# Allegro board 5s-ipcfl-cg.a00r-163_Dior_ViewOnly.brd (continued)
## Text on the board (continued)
BOTTOM: list("[Physical] BOTTOM" "210.Pad/Pad Direct Connect" "NOT_ALLOWED [(GND_20)]" "ALL_ALLOWED" "" "DRC ERROR CLASS/BOTTOM" "[SmdPin] GND (<uTiL>cId5786<uTiL>.33) (-2968.74 1.19)" "[ThruPin] GND (<uTiL>cId5786<uTiL>.35) (-3027.74 60.19)" list(-3027.740000 60.190000) nil)@@@list("eric2_tseng" "2019/01/23 17:34:51" nil "p143000044-pc" "5s-ipcfl-cg.a00r")@@@list("doris_chen" "2019/01/24 12:53:11" nil "p16c000356-pc" "5s-ipcfl-cg.a00r-chk") | list("[Physical] BOTTOM" "224.Pad/Pad Direct Connect" "NOT_ALLOWED [(GND_20)]" "ALL_ALLOWED" "" "DRC ERROR CLASS/BOTTOM" "[SmdPin] GND (<uTiL>cId5786<uTiL>.33) (-2968.74 1.19)" "[ThruPin] GND (<uTiL>cId5786<uTiL>.37) (-3027.74 -57.81)" list(-3027.740000 -57.810000) nil)@@@list("eric2_tseng" "2019/01/23 17:34:51" nil "p143000044-pc" "5s-ipcfl-cg.a00r")@@@list("doris_chen" "2019/01/24 12:53:19" nil "p16c000356-pc" "5s-ipcfl-cg.a00r-chk") | list("[Physical] BOTTOM" "234.Pad/Pad Direct Connect" "NOT_ALLOWED [(GND_20)]" "ALL_ALLOWED" "" "DRC ERROR CLASS/BOTTOM" "[SmdPin] GND (<uTiL>cId5786<uTiL>.33) (-2968.74 1.19)" "[ThruPin] GND (<uTiL>cId5786<uTiL>.34) (-2909.74 60.19)" list(-2909.740000 60.190000) nil)@@@list("eric2_tseng" "2019/01/23 17:34:51" nil "p143000044-pc" "5s-ipcfl-cg.a00r")@@@list("doris_chen" "2019/01/24 12:53:32" nil "p16c000356-pc" "5s-ipcfl-cg.a00r-chk") | list("[Physical] BOTTOM" "246.Pad/Pad Direct Connect" "NOT_ALLOWED [(GND_20)]" "ALL_ALLOWED" "" "DRC ERROR CLASS/BOTTOM" "[SmdPin] GND (<uTiL>cId5786<uTiL>.33) (-2968.74 1.19)" "[ThruPin] GND (<uTiL>cId5786<uTiL>.36) (-2909.74 -57.81)" list(-2909.740000 -57.810000) nil)@@@list("eric2_tseng" "2019/01/23 17:34:50" nil "p143000044-pc" "5s-ipcfl-cg.a00r")@@@list("doris_chen" "2019/01/24 12:53:38" nil "p16c000356-pc" "5s-ipcfl-cg.a00r-chk") | list("[Physical] BOTTOM" "223.Pad/Pad Direct Connect" "NOT_ALLOWED [(GND_20)]" "ALL_ALLOWED" "" "DRC ERROR CLASS/BOTTOM" "[SmdPin] GND (<uTiL>cId23<uTiL>.33) (-2750.0 2795.0)" "[ThruPin] GND (<uTiL>cId23<uTiL>.37) (-2790.5 2835.5)" list(-2790.500000 2835.500000) nil)@@@list("eric2_tseng" "2019/01/23 17:34:50" nil "p143000044-pc" "5s-ipcfl-cg.a00r")@@@list("doris_chen" "2019/01/24 12:53:18" nil "p16c000356-pc" "5s-ipcfl-cg.a00r-chk") | list("[Physical] BOTTOM" "222.Pad/Pad Direct Connect" "NOT_ALLOWED [(GND_20)]" "ALL_ALLOWED" "" "DRC ERROR CLASS/BOTTOM" "[ThruPin] GND (<uTiL>cId23<uTiL>.41) (-2790.5 2754.5)" "[SmdPin] GND (<uTiL>cId23<uTiL>.33) (-2750.0 2795.0)" list(-2790.500000 2754.500000) nil)@@@list("eric2_tseng" "2019/01/23 17:34:54" nil "p143000044-pc" "5s-ipcfl-cg.a00r")@@@list("doris_chen" "2019/01/24 12:53:18" nil "p16c000356-pc" "5s-ipcfl-cg.a00r-chk") | list("[Physical] BOTTOM" "244.Pad/Pad Direct Connect" "NOT_ALLOWED [(GND_20)]" "ALL_ALLOWED" "" "DRC ERROR CLASS/BOTTOM" "[SmdPin] GND (<uTiL>cId23<uTiL>.33) (-2750.0 2795.0)" "[ThruPin] GND (<uTiL>cId23<uTiL>.36) (-2770.5 2835.5)" list(-2770.500000 2835.500000) nil)@@@list("eric2_tseng" "2019/01/23 17:34:46" nil "p143000044-pc" "5s-ipcfl-cg.a00r")@@@list("doris_chen" "2019/01/24 12:53:38" nil "p16c000356-pc" "5s-ipcfl-cg.a00r-chk") | list("[Physical] BOTTOM" "221.Pad/Pad Direct Connect" "NOT_ALLOWED [(GND_20)]" "ALL_ALLOWED" "" "DRC ERROR CLASS/BOTTOM" "[ThruPin] GND (<uTiL>cId23<uTiL>.40) (-2770.5 2754.5)" "[SmdPin] GND (<uTiL>cId23<uTiL>.33) (-2750.0 2795.0)" list(-2770.500000 2754.500000) nil)@@@list("eric2_tseng" "2019/01/23 17:34:45" nil "p143000044-pc" "5s-ipcfl-cg.a00r")@@@list("doris_chen" "2019/01/24 12:53:17" nil "p16c000356-pc" "5s-ipcfl-cg.a00r-chk") | list("[Physical] BOTTOM" "220.Pad/Pad Direct Connect" "NOT_ALLOWED [(GND_20)]" "ALL_ALLOWED" "" "DRC ERROR CLASS/BOTTOM" "[ThruPin] GND (<uTiL>cId23<uTiL>.35) (-2729.5 2835.5)" "[SmdPin] GND (<uTiL>cId23<uTiL>.33) (-2750.0 2795.0)" list(-2729.500000 2835.500000) nil)@@@list("eric2_tseng" "2019/01/23 17:34:46" nil "p143000044-pc" "5s-ipcfl-cg.a00r")@@@list("doris_chen" "2019/01/24 12:53:17" nil "p16c000356-pc" "5s-ipcfl-cg.a00r-chk") | list("[Physical] BOTTOM" "236.Pad/Pad Direct Connect" "NOT_ALLOWED [(GND_20)]" "ALL_ALLOWED" "" "DRC ERROR CLASS/BOTTOM" "[SmdPin] GND (<uTiL>cId23<uTiL>.33) (-2750.0 2795.0)" "[ThruPin] GND (<uTiL>cId23<uTiL>.39) (-2729.5 2754.5)" list(-2729.500000 2754.500000) nil)@@@list("eric2_tseng" "2019/01/23 17:34:45" nil "p143000044-pc" "5s-ipcfl-cg.a00r")@@@list("doris_chen" "2019/01/24 12:53:33" nil "p16c000356-pc" "5s-ipcfl-cg.a00r-chk") | list("[Spacing] BOTTOM" "35.Shape to Route Keepin" "0 MIL [DEFAULT]" "0 MIL" "0.00 MIL" "DRC ERROR CLASS/BOTTOM" "[Shape] Route Keepin/All ((-3483.94 -2629.6) (3168.97 4113.86))" "[Bottom Shape] GND ((-2728.23 -2401.25) (-2614.45 -2219.63))" list(-2728.030000 -2224.450000) nil)@@@list("eric2_tseng" "2019/01/23 17:32:48" nil "p143000044-pc" "5s-ipcfl-cg.a00r")@@@list("doris_chen" "2019/01/24 12:51:31" nil "p16c000356-pc" "5s-ipcfl-cg.a00r-chk") | list("[Physical] BOTTOM" "219.Pad/Pad Direct Connect" "NOT_ALLOWED [(GND_20)]" "ALL_ALLOWED" "" "DRC ERROR CLASS/BOTTOM" "[ThruPin] GND (<uTiL>cId23<uTiL>.34) (-2709.5 2835.5)" "[SmdPin] GND (<uTiL>cId23<uTiL>.33) (-2750.0 2795.0)" list(-2709.500000 2835.500000) nil)@@@list("eric2_tseng" "2019/01/23 17:34:54" nil "p143000044-pc" "5s-ipcfl-cg.a00r")@@@list("doris_chen" "2019/01/24 12:53:16" nil "p16c000356-pc" "5s-ipcfl-cg.a00r-chk") | list("[Physical] BOTTOM" "233.Pad/Pad Direct Connect" "NOT_ALLOWED [(GND_20)]" "ALL_ALLOWED" "" "DRC ERROR CLASS/BOTTOM" "[SmdPin] GND (<uTiL>cId23<uTiL>.33) (-2750.0 2795.0)" "[ThruPin] GND (<uTiL>cId23<uTiL>.38) (-2709.5 2754.5)" list(-2709.500000 2754.500000) nil)@@@list("eric2_tseng" "2019/01/23 17:34:57" nil "p143000044-pc" "5s-ipcfl-cg.a00r")@@@list("doris_chen" "2019/01/24 12:53:32" nil "p16c000356-pc" "5s-ipcfl-cg.a00r-chk") | list("[Physical] BOTTOM" "245.Pad/Pad Direct Connect" "NOT_ALLOWED [DEFAULT]" "ALL_ALLOWED" "" "DRC ERROR CLASS/BOTTOM" "[ThruPin] PCH_HEATSINK_DET (<uTiL>cId6011<uTiL>.4) (-2152.51 -10.63)" "[ThruPin] PCH_HEATSINK_DET (<uTiL>cId5725<uTiL>.1) (-2152.52 -10.63)" list(-2152.520000 -10.630000) nil)@@@list("eric2_tseng" "2019/01/23 17:35:00" nil "p143000044-pc" "5s-ipcfl-cg.a00r")@@@list("doris_chen" "2019/01/24 12:53:38" nil "p16c000356-pc" "5s-ipcfl-cg.a00r-chk") | list("[Physical] BOTTOM" "237.Pad/Pad Direct Connect" "NOT_ALLOWED [DEFAULT]" "ALL_ALLOWED" "" "DRC ERROR CLASS/BOTTOM" "[ThruPin] PCH_HEATSINK_DET (<uTiL>cId5725<uTiL>.2) (-2152.52 189.37)" "[ThruPin] PCH_HEATSINK_DET (<uTiL>cId6011<uTiL>.3) (-2152.51 189.37)" list(-2152.510000 189.370000) nil)@@@list("eric2_tseng" "2019/01/23 17:34:59" nil "p143000044-pc" "5s-ipcfl-cg.a00r")@@@list("doris_chen" "2019/01/24 12:53:34" nil "p16c000356-pc" "5s-ipcfl-cg.a00r-chk") | list("[Spacing] BOTTOM" "33.Shape to Route Keepin" "0 MIL [DEFAULT]" "0 MIL" "0.00 MIL" "DRC ERROR CLASS/BOTTOM" "[Shape] Route Keepin/All ((-3483.94 -2629.6) (3168.97 4113.86))" "[Bottom Shape] GND ((-1658.98 -2629.61) (-814.86 -2440.41))" list(-1658.980000 -2629.600000) nil)@@@list("eric2_tseng" "2019/01/23 17:32:47" nil "p143000044-pc" "5s-ipcfl-cg.a00r")@@@list("doris_chen" "2019/01/24 12:51:30" nil "p16c000356-pc" "5s-ipcfl-cg.a00r-chk") | list("[Physical] BOTTOM" "225.Pad/Pad Direct Connect" "NOT_ALLOWED [(GND_20)]" "ALL_ALLOWED" "" "DRC ERROR CLASS/BOTTOM" "[SmdPin] GND (<uTiL>cId5609<uTiL>.9) (-975.0 -445.0)" "[ThruPin] GND (<uTiL>cId5609<uTiL>.11) (-1034.0 -404.0)" list(-1034.000000 -404.000000) nil)@@@list("eric2_tseng" "2019/01/23 17:34:47" nil "p143000044-pc" "5s-ipcfl-cg.a00r")@@@list("doris_chen" "2019/01/24 12:53:19" nil "p16c000356-pc" "5s-ipcfl-cg.a00r-chk") | list("[Physical] BOTTOM" "211.Pad/Pad Direct Connect" "NOT_ALLOWED [(GND_20)]" "ALL_ALLOWED" "" "DRC ERROR CLASS/BOTTOM" "[ThruPin] GND (<uTiL>cId5609<uTiL>.13) (-1034.0 -486.0)" "[SmdPin] GND (<uTiL>cId5609<uTiL>.9) (-975.0 -445.0)" list(-1034.000000 -486.000000) nil)@@@list("eric2_tseng" "2019/01/23 17:34:58" nil "p143000044-pc" "5s-ipcfl-cg.a00r")@@@list("doris_chen" "2019/01/24 12:53:12" nil "p16c000356-pc" "5s-ipcfl-cg.a00r-chk") | list("[Physical] BOTTOM" "240.Pad/Pad Direct Connect" "NOT_ALLOWED [(GND_20)]" "ALL_ALLOWED" "" "DRC ERROR CLASS/BOTTOM" "[SmdPin] GND (<uTiL>cId5609<uTiL>.9) (-975.0 -445.0)" "[ThruPin] GND (<uTiL>cId5609<uTiL>.10) (-916.0 -404.0)" list(-916.000000 -404.000000) nil)@@@list("eric2_tseng" "2019/01/23 17:34:47" nil "p143000044-pc" "5s-ipcfl-cg.a00r")@@@list("doris_chen" "2019/01/24 12:53:35" nil "p16c000356-pc" "5s-ipcfl-cg.a00r-chk") | list("[Physical] BOTTOM" "212.Pad/Pad Direct Connect" "NOT_ALLOWED [(GND_20)]" "ALL_ALLOWED" "" "DRC ERROR CLASS/BOTTOM" "[SmdPin] GND (<uTiL>cId5609<uTiL>.9) (-975.0 -445.0)" "[ThruPin] GND (<uTiL>cId5609<uTiL>.12) (-916.0 -486.0)" list(-916.000000 -486.000000) nil)@@@list("eric2_tseng" "2019/01/23 17:34:46" nil "p143000044-pc" "5s-ipcfl-cg.a00r")@@@list("doris_chen" "2019/01/24 12:53:12" nil "p16c000356-pc" "5s-ipcfl-cg.a00r-chk") | list("[Spacing-SameNet] BOTTOM" "43.Thru Pin to Thru Pin Same Net" "5 MIL [DEFAULT]" "OVERLAP" "" "DRC ERROR CLASS/BOTTOM" "[ThruPin] GND (<uTiL>cId5726<uTiL>.1) (-794.25 1790.95)" "[ThruPin] GND (<uTiL>cId6011<uTiL>.2) (-794.25 1790.95)" list(-794.250000 1790.950000) nil)@@@list("eric2_tseng" "2019/01/23 17:33:05" nil "p143000044-pc" "5s-ipcfl-cg.a00r")@@@list("doris_chen" "2019/01/24 12:51:35" nil "p16c000356-pc" "5s-ipcfl-cg.a00r-chk") | list("[Physical] BOTTOM" "238.Pad/Pad Direct Connect" "NOT_ALLOWED [80OHM(DP_5/4/5/200)]" "ALL_ALLOWED" "" "DRC ERROR CLASS/BOTTOM" "[SmdPin] USB3_RXN3_B1 (<uTiL>cId4780<uTiL>.2) (-766.56 3196.76)" "[SmdPin] USB3_RXN3_B1 (<uTiL>cId4874<uTiL>.3) (-768.81 3196.68)" list(-768.810000 3196.680000) nil)@@@list("eric2_tseng" "2019/01/23 17:34:55" nil "p143000044-pc" "5s-ipcfl-cg.a00r")@@@list("doris_chen" "2019/01/24 12:53:34" nil "p16c000356-pc" "5s-ipcfl-cg.a00r-chk") | list("[Physical] BOTTOM" "229.Pad/Pad Direct Connect" "NOT_ALLOWED [85OHM(DP_5|5/5|5.5/5/200)]" "ALL_ALLOWED" "" "DRC ERROR CLASS/BOTTOM" "[SmdPin] USB3_RXN3_B1_R (<uTiL>cId4874<uTiL>.4) (-768.81 3219.32)" "[SmdPin] USB3_RXN3_B1_R (<uTiL>cId4780<uTiL>.1) (-766.56 3220.38)" list(-766.560000 3220.380000) nil)@@@list("eric2_tseng" "2019/01/23 17:34:59" nil "p143000044-pc" "5s-ipcfl-cg.a00r")@@@list("doris_chen" "2019/01/24 12:53:21" nil "p16c000356-pc" "5s-ipcfl-cg.a00r-chk") | list("[Spacing-SameNet] BOTTOM" "44.Thru Pin to Thru Pin Same Net" "5 MIL [DEFAULT]" "OVERLAP" "" "DRC ERROR CLASS/BOTTOM" "[ThruPin] GND (<uTiL>cId5726<uTiL>.2) (-794.25 1990.95)" "[ThruPin] GND (<uTiL>cId6011<uTiL>.1) (-794.25 1990.95)" list(-759.750000 1990.950000) nil)@@@list("eric2_tseng" "2019/01/23 17:33:06" nil "p143000044-pc" "5s-ipcfl-cg.a00r")@@@list("doris_chen" "2019/01/24 12:51:36" nil "p16c000356-pc" "5s-ipcfl-cg.a00r-chk") | list("[Physical] BOTTOM" "249.Pad/Pad Direct Connect" "NOT_ALLOWED [85OHM(DP_5|5/5|5.5/5/200)]" "ALL_ALLOWED" "" "DRC ERROR CLASS/BOTTOM" "[SmdPin] USB3_RXP3_B1_R (<uTiL>cId4874<uTiL>.2) (-745.19 3219.32)" "[SmdPin] USB3_RXP3_B1_R (<uTiL>cId4780<uTiL>.4) (-746.88 3220.38)" list(-746.880000 3220.380000) nil)@@@list("eric2_tseng" "2019/01/23 17:35:02" nil "p143000044-pc" "5s-ipcfl-cg.a00r")@@@list("doris_chen" "2019/01/24 12:53:40" nil "p16c000356-pc" "5s-ipcfl-cg.a00r-chk") | list("[Physical] BOTTOM" "235.Pad/Pad Direct Connect" "NOT_ALLOWED [80OHM(DP_5/4/5/200)]" "ALL_ALLOWED" "" "DRC ERROR CLASS/BOTTOM" "[SmdPin] USB3_RXP3_B1 (<uTiL>cId4874<uTiL>.1) (-745.19 3196.68)" "[SmdPin] USB3_RXP3_B1 (<uTiL>cId4780<uTiL>.3) (-746.88 3196.76)" list(-746.880000 3196.760000) nil)@@@list("eric2_tseng" "2019/01/23 17:35:02" nil "p143000044-pc" "5s-ipcfl-cg.a00r")@@@list("doris_chen" "2019/01/24 12:53:33" nil "p16c000356-pc" "5s-ipcfl-cg.a00r-chk") | list("[Physical] BOTTOM" "247.Pad/Pad Direct Connect" "NOT_ALLOWED [85OHM(DP_5|5/5|5.5/5/200)]" "ALL_ALLOWED" "" "DRC ERROR CLASS/BOTTOM" "[SmdPin] USB3_TXN3_B1_R (<uTiL>cId4779<uTiL>.1) (-692.41 3197.09)" "[SmdPin] USB3_TXN3_B1_R (<uTiL>cId4877<uTiL>.4) (-694.38 3196.6)" list(-694.380000 3196.600000) nil)@@@list("eric2_tseng" "2019/01/23 17:34:49" nil "p143000044-pc" "5s-ipcfl-cg.a00r")@@@list("doris_chen" "2019/01/24 12:53:39" nil "p16c000356-pc" "5s-ipcfl-cg.a00r-chk") | list("[Physical] BOTTOM" "209.Pad/Pad Direct Connect" "NOT_ALLOWED [85OHM(DP_5|5/5|5.5/5/200)]" "ALL_ALLOWED" "" "DRC ERROR CLASS/BOTTOM" "[SmdPin] USB3_TXN3_B1 (<uTiL>cId4877<uTiL>.3) (-694.38 3173.96)" "[SmdPin] USB3_TXN3_B1 (<uTiL>cId4779<uTiL>.2) (-692.41 3173.47)" list(-692.410000 3173.470000) nil)@@@list("eric2_tseng" "2019/01/23 17:34:44" nil "p143000044-pc" "5s-ipcfl-cg.a00r")@@@list("doris_chen" "2019/01/24 12:53:11" nil "p16c000356-pc" "5s-ipcfl-cg.a00r-chk") | list("[Physical] BOTTOM" "250.Pad/Pad Direct Connect" "NOT_ALLOWED [85OHM(DP_5|5/5|5.5/5/200)]" "ALL_ALLOWED" "" "DRC ERROR CLASS/BOTTOM" "[SmdPin] USB3_TXP3_B1 (<uTiL>cId4877<uTiL>.1) (-670.76 3173.96)" "[SmdPin] USB3_TXP3_B1 (<uTiL>cId4779<uTiL>.3) (-672.73 3173.47)" list(-672.730000 3173.470000) nil)@@@list("eric2_tseng" "2019/01/23 17:34:55" nil "p143000044-pc" "5s-ipcfl-cg.a00r")@@@list("doris_chen" "2019/01/24 12:53:41" nil "p16c000356-pc" "5s-ipcfl-cg.a00r-chk") | list("[Physical] BOTTOM" "239.Pad/Pad Direct Connect" "NOT_ALLOWED [85OHM(DP_5|5/5|5.5/5/200)]" "ALL_ALLOWED" "" "DRC ERROR CLASS/BOTTOM" "[SmdPin] USB3_TXP3_B1_R (<uTiL>cId4779<uTiL>.4) (-672.73 3197.09)" "[SmdPin] USB3_TXP3_B1_R (<uTiL>cId4877<uTiL>.2) (-670.76 3196.6)" list(-670.760000 3196.600000) nil)@@@list("eric2_tseng" "2019/01/23 17:35:03" nil "p143000044-pc" "5s-ipcfl-cg.a00r")@@@list("doris_chen" "2019/01/24 12:53:35" nil "p16c000356-pc" "5s-ipcfl-cg.a00r-chk") | list("[Spacing] BOTTOM" "34.Drill Hole to Drill Hole" "8 MIL [DEFAULT]" "OVERLAP" "" "DRC ERROR CLASS/BOTTOM" "[ThruPin] Dummy (<uTiL>cId3746<uTiL>.2) (-359.85 883.07)" "[ThruPin] Dummy (<uTiL>cId3746<uTiL>.1) (-359.85 932.28)" list(-359.850000 847.780000) nil)@@@list("eric2_tseng" "2019/01/23 17:32:47" nil "p143000044-pc" "5s-ipcfl-cg.a00r")@@@list("doris_chen" "2019/01/24 12:51:31" nil "p16c000356-pc" "5s-ipcfl-cg.a00r-chk") | list("[Spacing] BOTTOM" "32.Drill Hole to Drill Hole" "8 MIL [DEFAULT]" "OVERLAP" "" "DRC ERROR CLASS/BOTTOM" "[ThruPin] Dummy (<uTiL>cId864<uTiL>.1) (-334.64 -788.19)" "[ThruPin] Dummy (<uTiL>cId864<uTiL>.2) (-334.64 -868.11)" list(-334.640000 -866.690000) nil)@@@list("eric2_tseng" "2019/01/23 17:32:48" nil "p143000044-pc" "5s-ipcfl-cg.a00r")@@@list("doris_chen" "2019/01/24 12:51:30" nil "p16c000356-pc" "5s-ipcfl-cg.a00r-chk") | list("[Physical] BOTTOM" "243.Pad/Pad Direct Connect" "NOT_ALLOWED [(GND_20)]" "ALL_ALLOWED" "" "DRC ERROR CLASS/BOTTOM" "[SmdPin] GND (<uTiL>cId5665<uTiL>.53) (110.0 3760.0)" "[ThruPin] GND (<uTiL>cId5665<uTiL>.56) (28.01 3841.99)" list(28.010000 3841.990000) nil)@@@list("eric2_tseng" "2019/01/23 17:35:00" nil "p143000044-pc" "5s-ipcfl-cg.a00r")@@@list("doris_chen" "2019/01/24 12:53:37" nil "p16c000356-pc" "5s-ipcfl-cg.a00r-chk") | list("[Physical] BOTTOM" "228.Pad/Pad Direct Connect" "NOT_ALLOWED [(GND_20)]" "ALL_ALLOWED" "" "DRC ERROR CLASS/BOTTOM" "[ThruPin] GND (<uTiL>cId5665<uTiL>.54) (28.01 3678.01)" "[SmdPin] GND (<uTiL>cId5665<uTiL>.53) (110.0 3760.0)" list(28.010000 3678.010000) nil)@@@list("eric2_tseng" "2019/01/23 17:35:01" nil "p143000044-pc" "5s-ipcfl-cg.a00r")@@@list("doris_chen" "2019/01/24 12:53:21" nil "p16c000356-pc" "5s-ipcfl-cg.a00r-chk") | list("[Physical] BOTTOM" "226.Pad/Pad Direct Connect" "NOT_ALLOWED [(GND_20)]" "ALL_ALLOWED" "" "DRC ERROR CLASS/BOTTOM" "[ThruPin] GND (<uTiL>cId5665<uTiL>.57) (191.99 3841.99)" "[SmdPin] GND (<uTiL>cId5665<uTiL>.53) (110.0 3760.0)" list(191.990000 3841.990000) nil)@@@list("eric2_tseng" "2019/01/23 17:35:00" nil "p143000044-pc" "5s-ipcfl-cg.a00r")@@@list("doris_chen" "2019/01/24 12:53:20" nil "p16c000356-pc" "5s-ipcfl-cg.a00r-chk") | list("[Physical] BOTTOM" "227.Pad/Pad Direct Connect" "NOT_ALLOWED [(GND_20)]" "ALL_ALLOWED" "" "DRC ERROR CLASS/BOTTOM" "[ThruPin] GND (<uTiL>cId5665<uTiL>.55) (191.99 3678.01)" "[SmdPin] GND (<uTiL>cId5665<uTiL>.53) (110.0 3760.0)" list(191.990000 3678.010000) nil)@@@list("eric2_tseng" "2019/01/23 17:35:01" nil "p143000044-pc" "5s-ipcfl-cg.a00r")@@@list("doris_chen" "2019/01/24 12:53:20" nil "p16c000356-pc" "5s-ipcfl-cg.a00r-chk") | list("[Physical] BOTTOM" "248.Pad/Pad Direct Connect" "NOT_ALLOWED [(GND_20)]" "ALL_ALLOWED" "" "DRC ERROR CLASS/BOTTOM" "[SmdPin] GND (<uTiL>cId2568<uTiL>.9) (290.43 -1049.72)" "[ThruPin] GND (<uTiL>cId2568<uTiL>.10) (249.43 -990.72)" list(249.430000 -990.720000) nil)@@@list("eric2_tseng" "2019/01/23 17:34:58" nil "p143000044-pc" "5s-ipcfl-cg.a00r")@@@list("doris_chen" "2019/01/24 12:53:40" nil "p16c000356-pc" "5s-ipcfl-cg.a00r-chk") | list("[Physical] BOTTOM" "213.Pad/Pad Direct Connect" "NOT_ALLOWED [(GND_20)]" "ALL_ALLOWED" "" "DRC ERROR CLASS/BOTTOM" "[ThruPin] GND (<uTiL>cId2568<uTiL>.11) (249.43 -1108.72)" "[SmdPin] GND (<uTiL>cId2568<uTiL>.9) (290.43 -1049.72)" list(249.430000 -1108.720000) nil)@@@list("eric2_tseng" "2019/01/23 17:34:48" nil "p143000044-pc" "5s-ipcfl-cg.a00r")@@@list("doris_chen" "2019/01/24 12:53:13" nil "p16c000356-pc" "5s-ipcfl-cg.a00r-chk") | list("[Physical] BOTTOM" "241.Pad/Pad Direct Connect" "NOT_ALLOWED [(GND_20)]" "ALL_ALLOWED" "" "DRC ERROR CLASS/BOTTOM" "[SmdPin] GND (<uTiL>cId2568<uTiL>.9) (290.43 -1049.72)" "[ThruPin] GND (<uTiL>cId2568<uTiL>.12) (331.43 -990.72)" list(331.430000 -990.720000) nil)@@@list("eric2_tseng" "2019/01/23 17:34:49" nil "p143000044-pc" "5s-ipcfl-cg.a00r")@@@list("doris_chen" "2019/01/24 12:53:36" nil "p16c000356-pc" "5s-ipcfl-cg.a00r-chk") | list("[Physical] BOTTOM" "242.Pad/Pad Direct Connect" "NOT_ALLOWED [(GND_20)]" "ALL_ALLOWED" "" "DRC ERROR CLASS/BOTTOM" "[SmdPin] GND (<uTiL>cId2568<uTiL>.9) (290.43 -1049.72)" "[ThruPin] GND (<uTiL>cId2568<uTiL>.13) (331.43 -1108.72)" list(331.430000 -1108.720000) nil)@@@list("eric2_tseng" "2019/01/23 17:34:48" nil "p143000044-pc" "5s-ipcfl-cg.a00r")@@@list("doris_chen" "2019/01/24 12:53:36" nil "p16c000356-pc" "5s-ipcfl-cg.a00r-chk") | list("[Physical] BOTTOM" "214.Pad/Pad Direct Connect" "NOT_ALLOWED [(GND_20)]" "ALL_ALLOWED" "" "DRC ERROR CLASS/BOTTOM" "[ThruPin] GND (<uTiL>cId2174<uTiL>.25) (744.93 -1489.22)" "[SmdPin] GND (<uTiL>cId2174<uTiL>.21) (765.43 -1509.72)" list(744.930000 -1489.220000) nil)@@@list("eric2_tseng" "2019/01/23 17:34:57" nil "p143000044-pc" "5s-ipcfl-cg.a00r")@@@list("doris_chen" "2019/01/24 12:53:13" nil "p16c000356-pc" "5s-ipcfl-cg.a00r-chk") | list("[Physical] BOTTOM" "230.Pad/Pad Direct Connect" "NOT_ALLOWED [(GND_20)]" "ALL_ALLOWED" "" "DRC ERROR CLASS/BOTTOM" "[SmdPin] GND (<uTiL>cId2174<uTiL>.21) (765.43 -1509.72)" "[ThruPin] GND (<uTiL>cId2174<uTiL>.24) (744.93 -1530.22)" list(744.930000 -1530.220000) nil)@@@list("eric2_tseng" "2019/01/23 17:34:56" nil "p143000044-pc" "5s-ipcfl-cg.a00r")@@@list("doris_chen" "2019/01/24 12:53:22" nil "p16c000356-pc" "5s-ipcfl-cg.a00r-chk") | list("[Physical] BOTTOM" "215.Pad/Pad Direct Connect" "NOT_ALLOWED [(GND_20)]" "ALL_ALLOWED" "" "DRC ERROR CLASS/BOTTOM" "[SmdPin] GND (<uTiL>cId2174<uTiL>.21) (765.43 -1509.72)" "[ThruPin] GND (<uTiL>cId2174<uTiL>.23) (785.93 -1489.22)" list(785.930000 -1489.220000) nil)@@@list("eric2_tseng" "2019/01/23 17:34:56" nil "p143000044-pc" "5s-ipcfl-cg.a00r")@@@list("doris_chen" "2019/01/24 12:53:14" nil "p16c000356-pc" "5s-ipcfl-cg.a00r-chk") | list("[Physical] BOTTOM" "218.Pad/Pad Direct Connect" "NOT_ALLOWED [(GND_20)]" "ALL_ALLOWED" "" "DRC ERROR CLASS/BOTTOM" "[SmdPin] GND (<uTiL>cId2174<uTiL>.21) (765.43 -1509.72)" "[ThruPin] GND (<uTiL>cId2174<uTiL>.22) (785.93 -1530.22)" list(785.930000 -1530.220000) nil)@@@list("eric2_tseng" "2019/01/23 17:34:56" nil "p143000044-pc" "5s-ipcfl-cg.a00r")@@@list("doris_chen" "2019/01/24 12:53:16" nil "p16c000356-pc" "5s-ipcfl-cg.a00r-chk") | list("[Physical] BOTTOM" "232.Pad/Pad Direct Connect" "NOT_ALLOWED [(GND_20)]" "ALL_ALLOWED" "" "DRC ERROR CLASS/BOTTOM" "[SmdPin] GND (<uTiL>cId2930<uTiL>.21) (1940.43 -1544.72)" "[ThruPin] GND (<uTiL>cId2930<uTiL>.25) (1919.93 -1524.22)" list(1919.930000 -1524.220000) nil)@@@list("eric2_tseng" "2019/01/23 17:34:52" nil "p143000044-pc" "5s-ipcfl-cg.a00r")@@@list("doris_chen" "2019/01/24 12:53:31" nil "p16c000356-pc" "5s-ipcfl-cg.a00r-chk") | list("[Physical] BOTTOM" "216.Pad/Pad Direct Connect" "NOT_ALLOWED [(GND_20)]" "ALL_ALLOWED" "" "DRC ERROR CLASS/BOTTOM" "[ThruPin] GND (<uTiL>cId2930<uTiL>.24) (1919.93 -1565.22)" "[SmdPin] GND (<uTiL>cId2930<uTiL>.21) (1940.43 -1544.72)" list(1919.930000 -1565.220000) nil)@@@list("eric2_tseng" "2019/01/23 17:34:53" nil "p143000044-pc" "5s-ipcfl-cg.a00r")@@@list("doris_chen" "2019/01/24 12:53:15" nil "p16c000356-pc" "5s-ipcfl-cg.a00r-chk") | list("[Physical] BOTTOM" "217.Pad/Pad Direct Connect" "NOT_ALLOWED [(GND_20)]" "ALL_ALLOWED" "" "DRC ERROR CLASS/BOTTOM" "[SmdPin] GND (<uTiL>cId2930<uTiL>.21) (1940.43 -1544.72)" "[ThruPin] GND (<uTiL>cId2930<uTiL>.23) (1960.93 -1524.22)" list(1960.930000 -1524.220000) nil)@@@list("eric2_tseng" "2019/01/23 17:34:52" nil "p143000044-pc" "5s-ipcfl-cg.a00r")@@@list("doris_chen" "2019/01/24 12:53:15" nil "p16c000356-pc" "5s-ipcfl-cg.a00r-chk") | list("[Physical] BOTTOM" "231.Pad/Pad Direct Connect" "NOT_ALLOWED [(GND_20)]" "ALL_ALLOWED" "" "DRC ERROR CLASS/BOTTOM" "[SmdPin] GND (<uTiL>cId2930<uTiL>.21) (1940.43 -1544.72)" "[ThruPin] GND (<uTiL>cId2930<uTiL>.22) (1960.93 -1565.22)" list(1960.930000 -1565.220000) nil)@@@list("eric2_tseng" "2019/01/23 17:34:53" nil "p143000044-pc" "5s-ipcfl-cg.a00r")@@@list("doris_chen" "2019/01/24 12:53:23" nil "p16c000356-pc" "5s-ipcfl-cg.a00r-chk")
Ref Des/Silkscreen Bottom: U104 | U7201 | U114 | XDP3 | Y4000 | XDP1 | PU89001 | PU4 | PU9 | PCB BARCODE
